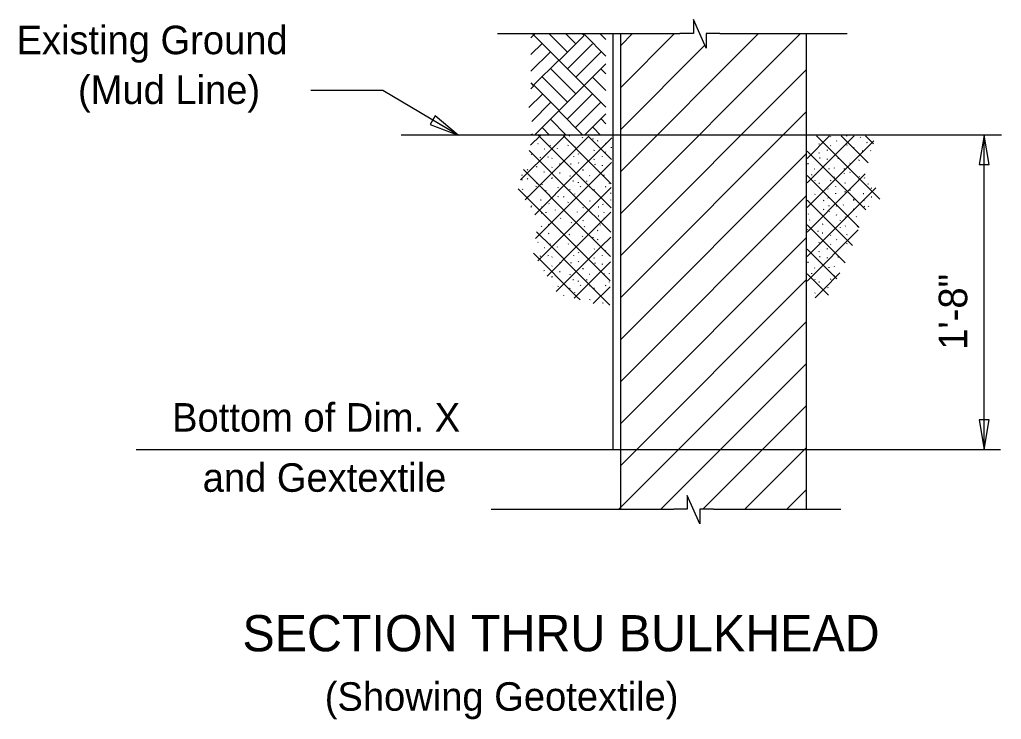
# Model space of a CAD drawing. Extents: x 0.4 to 30.4, y 0.1 to 19.4.
# Drawn here: x 9.23 to 14.44, y 10.56 to 14.27 of the extents above; entities that cross this region are included whole.
import ezdxf

# ---------------------------------------------------------------- set-up
doc = ezdxf.new("R2010")
doc.units = 0
for name, color, linetype in [('Dimension', 7, 'Continuous'), ('Miscellaneous', 7, 'Continuous'), ('Rebar', 7, 'Continuous'), ('SheetPileConc', 7, 'Continuous'), ('TextStructures', 7, 'Continuous')]:
    doc.layers.add(name, color=color, linetype=linetype)

msp = doc.modelspace()

# ---------------------------------------------------------------- linework, layer by layer
at = {"layer": 'Dimension'}
for p, q in [((11.7699, 14.197), (12.738, 14.197)), ((12.9487, 14.197), (13.6252, 14.197)), ((14.3518, 11.9905), (14.3518, 13.6572)), ((9.8519, 11.9905), (14.439, 11.9905)), ((11.737, 11.6738), (12.7051, 11.6738)), ((12.9158, 11.6738), (13.5923, 11.6738))]:
    msp.add_line(p, q, dxfattribs=at)
for points in [[(12.9487, 14.197), (12.8768, 14.197), (12.8768, 14.1188), (12.8099, 14.27), (12.8099, 14.197), (12.738, 14.197)], [(11.5605, 13.6572), (11.1618, 13.8946), (10.7797, 13.8946)], [(12.9158, 11.6738), (12.8439, 11.6738), (12.8439, 11.5957), (12.777, 11.7469), (12.777, 11.6738), (12.7051, 11.6738)]]:
    msp.add_lwpolyline(points, dxfattribs=at)
for points in [[(11.5605, 13.6572), (11.4399, 13.7599), (11.4128, 13.7144)], [(14.3517, 13.6572), (14.3253, 13.501), (14.3782, 13.501)], [(14.3517, 11.9906), (14.3782, 12.1468), (14.3253, 12.1468)]]:
    msp.add_lwpolyline(points, close=True, dxfattribs=at)
at = {"layer": 'Miscellaneous'}
for p, q in [((11.9706, 14.197), (11.9466, 14.1729)), ((12.0946, 14.0559), (11.9534, 14.197)), ((12.042, 14.197), (12.1388, 14.1002)), ((12.23, 14.1858), (12.0974, 14.0531)), ((12.1302, 14.197), (12.1829, 14.1443)), ((12.2188, 14.197), (12.2272, 14.1886)), ((12.2357, 14.197), (12.23, 14.1913)), ((12.3449, 14.0764), (12.2328, 14.1886)), ((12.3449, 14.1647), (12.3126, 14.197)), ((12.4236, 13.2427), (13.378, 14.197)), ((12.4236, 13.9109), (12.7097, 14.197)), ((12.4236, 13.4654), (13.1552, 14.197)), ((12.4236, 14.1336), (12.487, 14.197)), ((12.0062, 14.1443), (11.9466, 14.0847)), ((12.2743, 14.1415), (12.1416, 14.0088)), ((12.4236, 13.6881), (12.8699, 14.1345)), ((12.0503, 14.1002), (11.9466, 13.9964)), ((12.3184, 14.0974), (12.1857, 13.9647)), ((12.0946, 14.0559), (11.9624, 13.9238)), ((12.3449, 13.8056), (12.0974, 14.0531)), ((12.3449, 14.0362), (12.0975, 13.7887)), ((12.1416, 13.8329), (12.0093, 13.9651)), ((12.1859, 13.8772), (12.0536, 14.0094)), ((12.2739, 13.9651), (12.3449, 13.8941)), ((12.318, 14.0093), (12.3449, 13.9824)), ((12.4236, 13.0199), (13.408, 14.0043)), ((11.9466, 13.9341), (11.9597, 13.921)), ((11.9624, 13.9182), (11.9466, 13.9023)), ((12.0975, 13.7887), (11.9652, 13.921)), ((12.0067, 13.8739), (11.9361, 13.8033)), ((12.2737, 13.8768), (12.1416, 13.7446)), ((12.0509, 13.8298), (11.9512, 13.7301)), ((12.3178, 13.8326), (12.1857, 13.7005)), ((12.0947, 13.7859), (11.9661, 13.6572)), ((12.0947, 13.7859), (12.2234, 13.6572)), ((12.3449, 13.771), (12.2311, 13.6572)), ((12.4236, 12.7972), (13.408, 13.7816)), ((12.0504, 13.7417), (12.1348, 13.6572)), ((12.3449, 13.7182), (12.3212, 13.7419)), ((14.4433, 13.6572), (11.2587, 13.6572)), ((11.9455, 13.6035), (11.9975, 13.6555)), ((11.958, 13.6572), (11.9512, 13.6641)), ((12.0578, 13.5856), (11.9878, 13.6556)), ((12.0063, 13.6976), (12.0466, 13.6572)), ((12.0578, 13.5856), (12.1264, 13.6541)), ((12.1878, 13.5858), (12.1194, 13.6542)), ((12.1523, 13.6532), (12.1486, 13.6525)), ((12.1881, 13.5856), (12.2553, 13.6528)), ((12.2215, 13.6441), (12.2223, 13.6472)), ((12.3183, 13.5856), (12.251, 13.6529)), ((12.3172, 13.6572), (12.2769, 13.6976)), ((13.4129, 13.5345), (13.5321, 13.6537)), ((13.4129, 13.4043), (13.6623, 13.6537)), ((13.7576, 13.3588), (13.4626, 13.6537)), ((13.538, 13.6483), (13.5372, 13.6498)), ((13.7367, 13.5099), (13.5928, 13.6537)), ((13.6237, 13.6521), (13.624, 13.6537)), ((13.7578, 13.6189), (13.723, 13.6537)), ((11.9851, 13.6111), (11.9836, 13.6118)), ((12.0513, 13.6028), (12.0506, 13.6043)), ((12.1455, 13.6023), (12.1463, 13.6053)), ((12.1817, 13.5945), (12.1824, 13.5976)), ((12.2772, 13.6359), (12.2779, 13.6389)), ((12.3027, 13.6269), (12.2982, 13.6261)), ((12.3183, 13.5856), (12.3761, 13.6434)), ((12.3441, 13.614), (12.3434, 13.6155)), ((13.4763, 13.61), (13.4778, 13.613)), ((13.4974, 13.3585), (13.7578, 13.619)), ((13.538, 13.601), (13.5372, 13.6025)), ((13.5688, 13.6251), (13.5695, 13.6281)), ((13.6237, 13.6048), (13.6245, 13.6085)), ((13.6959, 13.6454), (13.6944, 13.6461)), ((13.7305, 13.6182), (13.7275, 13.6168)), ((13.7578, 13.6189), (13.7669, 13.628)), ((13.7646, 13.6122), (13.7578, 13.619)), ((13.7621, 13.6371), (13.7613, 13.6386)), ((11.8926, 13.4203), (12.0578, 13.5856)), ((11.9169, 13.3143), (12.1881, 13.5856)), ((12.1881, 13.3251), (11.9375, 13.5757)), ((11.9506, 13.5554), (11.9513, 13.5584)), ((12.0197, 13.584), (12.0167, 13.5825)), ((12.1881, 13.4554), (12.0578, 13.5856)), ((12.0881, 13.5862), (12.0888, 13.5892)), ((12.1749, 13.5419), (12.1757, 13.5449)), ((12.3735, 13.4001), (12.1881, 13.5856)), ((12.1881, 13.4554), (12.3183, 13.5856)), ((12.2005, 13.557), (12.2012, 13.5599)), ((12.2824, 13.5757), (12.2839, 13.5788)), ((12.3749, 13.5289), (12.3183, 13.5856)), ((12.3268, 13.5419), (12.3268, 13.5449)), ((12.3441, 13.5667), (12.3434, 13.5682)), ((12.3749, 13.5908), (12.3756, 13.5936)), ((12.4236, 12.5745), (13.408, 13.5588)), ((13.6276, 13.3585), (13.4129, 13.5732)), ((13.4763, 13.5626), (13.4778, 13.5656)), ((13.5207, 13.5762), (13.5207, 13.5792)), ((13.6613, 13.5897), (13.6621, 13.5927)), ((13.7087, 13.5724), (13.705, 13.5717)), ((13.7508, 13.5739), (13.7493, 13.5762)), ((11.9769, 13.49), (11.9784, 13.493)), ((11.9784, 13.4885), (11.9791, 13.4915)), ((11.9979, 13.5381), (11.9942, 13.5374)), ((12.04, 13.5396), (12.0385, 13.5419)), ((12.0588, 13.5329), (12.0603, 13.5359)), ((12.1022, 13.5036), (12.0984, 13.5028)), ((12.1614, 13.5036), (12.1576, 13.5028)), ((12.1881, 13.3251), (12.3747, 13.5118)), ((12.2005, 13.5088), (12.2012, 13.5118)), ((12.2824, 13.5284), (12.2839, 13.5314)), ((12.2877, 13.5013), (12.2847, 13.5006)), ((12.3268, 13.4945), (12.3268, 13.4975)), ((13.4199, 13.5055), (13.4154, 13.5055)), ((13.4816, 13.5356), (13.4786, 13.5348)), ((13.5207, 13.5288), (13.5207, 13.5318)), ((13.5793, 13.5341), (13.5756, 13.5333)), ((13.6387, 13.5063), (13.641, 13.5092)), ((13.6876, 13.5243), (13.6891, 13.5273)), ((13.6891, 13.5228), (13.6899, 13.5258)), ((11.9002, 13.4434), (11.9009, 13.4464)), ((12.1881, 13.1949), (11.9083, 13.4746)), ((11.928, 13.472), (11.9302, 13.4749)), ((11.9678, 13.235), (12.1881, 13.4554)), ((12.0197, 13.4599), (12.0182, 13.4622)), ((12.0588, 13.4855), (12.0603, 13.4885)), ((12.1022, 13.4562), (12.0984, 13.4554)), ((12.1557, 13.4404), (12.1565, 13.4434)), ((12.3721, 13.2713), (12.1881, 13.4554)), ((12.226, 13.4712), (12.2215, 13.4712)), ((12.2599, 13.4419), (12.2584, 13.4426)), ((12.335, 13.4434), (12.3358, 13.4464)), ((12.3644, 13.4479), (12.3637, 13.4494)), ((13.4974, 13.3585), (13.4129, 13.443)), ((13.4372, 13.4461), (13.438, 13.449)), ((13.4538, 13.4762), (13.4523, 13.4769)), ((13.5289, 13.4777), (13.5297, 13.4807)), ((13.5583, 13.4822), (13.5576, 13.4837)), ((13.6109, 13.4777), (13.6117, 13.4807)), ((13.6109, 13.4536), (13.6117, 13.4566)), ((13.6276, 13.3585), (13.7209, 13.4518)), ((13.6387, 13.4589), (13.641, 13.4619)), ((11.9002, 13.4193), (11.9009, 13.4223)), ((11.928, 13.4246), (11.9302, 13.4276)), ((11.9746, 13.3855), (11.9761, 13.3886)), ((11.9784, 13.4013), (11.9791, 13.4043)), ((12.0069, 13.3952), (12.0084, 13.399)), ((12.058, 13.4276), (12.0573, 13.4291)), ((12.0611, 13.4299), (12.058, 13.4299)), ((12.1734, 13.414), (12.1697, 13.4133)), ((12.1802, 13.3915), (12.1798, 13.3923)), ((12.199, 13.405), (12.1997, 13.4081)), ((12.2103, 13.3832), (12.2118, 13.387)), ((12.2434, 13.4118), (12.2441, 13.4148)), ((12.3644, 13.4006), (12.3637, 13.4021)), ((13.4546, 13.4145), (13.4561, 13.4175)), ((13.4786, 13.4017), (13.4749, 13.4009)), ((13.538, 13.4175), (13.5343, 13.416)), ((13.5583, 13.4348), (13.5576, 13.4363)), ((13.6139, 13.4032), (13.6155, 13.4069)), ((13.6854, 13.4198), (13.6869, 13.4228)), ((13.6891, 13.4356), (13.6899, 13.4386)), ((13.7177, 13.4295), (13.7192, 13.4333)), ((13.7372, 13.3972), (13.738, 13.4002)), ((12.1878, 13.0649), (11.8791, 13.3736)), ((11.9032, 13.369), (11.9047, 13.3727)), ((12.0265, 13.3629), (12.0272, 13.366)), ((12.0446, 13.3412), (12.0423, 13.3419)), ((12.0919, 13.378), (12.0934, 13.381)), ((12.1542, 13.3675), (12.1549, 13.3705)), ((12.1802, 13.3442), (12.1794, 13.3456)), ((12.1881, 13.1949), (12.3733, 13.3801)), ((12.2607, 13.3802), (12.2622, 13.3832)), ((12.2847, 13.3675), (12.281, 13.3667)), ((12.3306, 13.3359), (12.3283, 13.3382)), ((12.3441, 13.3832), (12.3404, 13.3817)), ((12.3704, 13.3487), (12.3712, 13.3516)), ((12.4236, 12.3517), (13.408, 13.3361)), ((13.4129, 13.0136), (13.7578, 13.3585)), ((13.4129, 13.274), (13.4974, 13.3585)), ((13.4129, 13.1438), (13.6276, 13.3585)), ((13.4541, 13.3419), (13.4549, 13.3448)), ((13.6887, 13.1672), (13.4974, 13.3585)), ((13.5245, 13.3702), (13.5222, 13.3724)), ((13.5643, 13.383), (13.5651, 13.3859)), ((13.5651, 13.3461), (13.5658, 13.3491)), ((13.6139, 13.3558), (13.6155, 13.3596)), ((13.724, 13.2621), (13.6276, 13.3585)), ((13.641, 13.3642), (13.6417, 13.3671)), ((13.7132, 13.3468), (13.7094, 13.3461)), ((13.7553, 13.3754), (13.7531, 13.3761)), ((13.7578, 13.3585), (13.7772, 13.3779)), ((13.7979, 13.3184), (13.7578, 13.3585)), ((11.9302, 13.3299), (11.931, 13.3328)), ((11.9506, 13.2817), (11.9513, 13.2848)), ((11.9722, 13.1093), (12.1881, 13.3251)), ((12.0024, 13.3125), (11.9986, 13.3118)), ((12.0446, 13.2938), (12.0423, 13.2945)), ((12.0919, 13.3306), (12.0934, 13.3336)), ((12.1214, 13.3289), (12.1221, 13.332)), ((12.1452, 13.3007), (12.1459, 13.3037)), ((12.3707, 13.1425), (12.1881, 13.3251)), ((12.2602, 13.3076), (12.261, 13.3106)), ((12.3306, 13.2886), (12.3283, 13.2908)), ((12.3712, 13.3118), (12.3719, 13.3149)), ((13.6536, 13.072), (13.4129, 13.3127)), ((13.4184, 13.3069), (13.4191, 13.31)), ((13.5019, 13.31), (13.4981, 13.3092)), ((13.5245, 13.3228), (13.5222, 13.325)), ((13.5289, 13.2806), (13.5297, 13.2837)), ((13.5688, 13.2806), (13.5695, 13.2837)), ((13.6041, 13.2856), (13.6049, 13.2885)), ((13.6598, 13.3107), (13.6613, 13.3138)), ((13.6613, 13.316), (13.6621, 13.319)), ((13.7143, 13.309), (13.715, 13.312)), ((13.7387, 13.2799), (13.7395, 13.2829)), ((13.7553, 13.328), (13.7531, 13.3288)), ((11.949, 13.2764), (11.9506, 13.2795)), ((12.0054, 13.2442), (12.0024, 13.2434)), ((12.0035, 13.2748), (12.0043, 13.2777)), ((12.028, 13.2456), (12.0287, 13.2486)), ((12.0769, 13.2592), (12.0776, 13.2622)), ((12.123, 13.257), (12.1245, 13.26)), ((12.1881, 13.0647), (12.3718, 13.2485)), ((12.1945, 13.2486), (12.1952, 13.2516)), ((12.2245, 13.2727), (12.2253, 13.2757)), ((12.308, 13.2757), (12.3042, 13.2749)), ((12.335, 13.2464), (12.3358, 13.2494)), ((13.4184, 13.2378), (13.4191, 13.2408)), ((13.5019, 13.2627), (13.4981, 13.2619)), ((13.5315, 13.2504), (13.5322, 13.2534)), ((13.5688, 13.2333), (13.5695, 13.2363)), ((13.6598, 13.2634), (13.6613, 13.2664)), ((13.7162, 13.2784), (13.7132, 13.2776)), ((12.0415, 13.1832), (12.0385, 13.1817)), ((12.0578, 13.0647), (12.1881, 13.1949)), ((12.1036, 13.2149), (12.1051, 13.2178)), ((12.1644, 13.1915), (12.1629, 13.1938)), ((12.3183, 13.0647), (12.1881, 13.1949)), ((12.2245, 13.2035), (12.2253, 13.2065)), ((12.308, 13.2284), (12.3042, 13.2276)), ((12.3163, 13.1795), (12.3171, 13.1824)), ((12.3376, 13.2162), (12.3383, 13.2191)), ((13.6145, 12.9809), (13.4129, 13.1825)), ((13.426, 13.2058), (13.4268, 13.2088)), ((13.4966, 13.1851), (13.4921, 13.1844)), ((13.5102, 13.2138), (13.5109, 13.2167)), ((13.5891, 13.2025), (13.5899, 13.2054)), ((13.6169, 13.2235), (13.6139, 13.2228)), ((13.6749, 13.2235), (13.6726, 13.2258)), ((12.0578, 13.0647), (11.9775, 13.1451)), ((12.0032, 13.1734), (12.0047, 13.1764)), ((12.0415, 13.1358), (12.0385, 13.1344)), ((12.1052, 13.1442), (12.1037, 13.1464)), ((12.1523, 13.1299), (12.1486, 13.1291)), ((12.2321, 13.1716), (12.2329, 13.1745)), ((12.3027, 13.1509), (12.2982, 13.1501)), ((13.4129, 12.8834), (13.684, 13.1545)), ((13.4154, 13.1551), (13.4162, 13.1581)), ((13.4711, 13.1468), (13.4718, 13.1498)), ((13.4966, 13.1378), (13.4921, 13.137)), ((13.538, 13.125), (13.5372, 13.1265)), ((13.5891, 13.1671), (13.5899, 13.1701)), ((13.6169, 13.1761), (13.6139, 13.1754)), ((13.6237, 13.1287), (13.6245, 13.1325)), ((13.6801, 13.1717), (13.6809, 13.1746)), ((11.9851, 13.0878), (11.9836, 13.0885)), ((12.0513, 13.0794), (12.0506, 13.0809)), ((12.1455, 13.0789), (12.1463, 13.0819)), ((12.1817, 13.0712), (12.1824, 13.0742)), ((12.2215, 13.1208), (12.2223, 13.1238)), ((12.2772, 13.1125), (12.2779, 13.1156)), ((12.3027, 13.1035), (12.2982, 13.1027)), ((12.3183, 13.0647), (12.3704, 13.1168)), ((12.3441, 13.0907), (12.3434, 13.0922)), ((12.4236, 12.129), (13.408, 13.1133)), ((13.4763, 13.0866), (13.4778, 13.0897)), ((13.538, 13.0776), (13.5372, 13.0791)), ((13.5688, 13.1017), (13.5695, 13.1047)), ((13.6237, 13.0814), (13.6245, 13.0851)), ((12.1881, 12.8042), (11.9608, 13.0315)), ((11.9843, 12.9911), (12.0578, 13.0647)), ((12.0197, 13.0606), (12.0167, 13.0592)), ((12.0331, 12.9097), (12.1881, 13.0647)), ((12.1881, 12.9345), (12.0578, 13.0647)), ((12.0881, 13.0629), (12.0888, 13.0659)), ((12.3679, 12.8848), (12.1881, 13.0647)), ((12.1881, 12.9345), (12.3183, 13.0647)), ((12.2005, 13.0336), (12.2012, 13.0366)), ((12.2824, 13.0524), (12.2839, 13.0554)), ((12.3693, 13.0136), (12.3183, 13.0647)), ((12.3441, 13.0434), (12.3434, 13.0449)), ((13.57, 12.8952), (13.4129, 13.0523)), ((13.4763, 13.0393), (13.4778, 13.0423)), ((13.5207, 13.0528), (13.5207, 13.0558)), ((11.9979, 13.0148), (11.9942, 13.0141)), ((12.04, 13.0163), (12.0385, 13.0186)), ((12.0588, 13.0095), (12.0603, 13.0125)), ((12.1022, 12.9802), (12.0984, 12.9794)), ((12.1614, 12.9802), (12.1576, 12.9794)), ((12.1749, 13.0186), (12.1757, 13.0216)), ((12.1881, 12.8042), (12.369, 12.9851)), ((12.2005, 12.9854), (12.2012, 12.9885)), ((12.2824, 13.005), (12.2839, 13.008)), ((12.2877, 12.9779), (12.2847, 12.9772)), ((12.3268, 13.0186), (12.3268, 13.0216)), ((12.3268, 12.9712), (12.3268, 12.9742)), ((13.4199, 12.9821), (13.4154, 12.9821)), ((13.4816, 13.0122), (13.4786, 13.0115)), ((13.5207, 13.0054), (13.5207, 13.0084)), ((13.5793, 13.0107), (13.5756, 13.0099)), ((12.0197, 12.9366), (12.0182, 12.9389)), ((12.0588, 12.9621), (12.0603, 12.9652)), ((12.0819, 12.8283), (12.1881, 12.9345)), ((12.1022, 12.9328), (12.0984, 12.932)), ((12.1557, 12.9171), (12.1565, 12.9201)), ((12.3665, 12.756), (12.1881, 12.9345)), ((12.226, 12.9479), (12.2215, 12.9479)), ((12.2599, 12.9186), (12.2584, 12.9193)), ((12.335, 12.9201), (12.3358, 12.9231)), ((12.3644, 12.9246), (12.3637, 12.9261)), ((13.4974, 12.8376), (13.4129, 12.9221)), ((13.4372, 12.9228), (13.438, 12.9257)), ((13.4538, 12.9528), (13.4523, 12.9536)), ((13.4974, 12.8376), (13.5864, 12.9266)), ((13.5289, 12.9543), (13.5297, 12.9573)), ((13.5583, 12.9588), (13.5576, 12.9603)), ((12.058, 12.9042), (12.0573, 12.9057)), ((12.0611, 12.9065), (12.058, 12.9065)), ((12.1734, 12.8907), (12.1697, 12.89)), ((12.1802, 12.8681), (12.1798, 12.869)), ((12.199, 12.8817), (12.1997, 12.8847)), ((12.2434, 12.8885), (12.2441, 12.8914)), ((12.3644, 12.8772), (12.3637, 12.8787)), ((12.4236, 11.9062), (13.408, 12.8906)), ((13.4546, 12.8911), (13.4561, 12.8941)), ((13.4786, 12.8784), (13.4749, 12.8776)), ((13.538, 12.8941), (13.5343, 12.8926)), ((13.5583, 12.9115), (13.5576, 12.913)), ((12.0919, 12.8547), (12.0934, 12.8577)), ((12.1542, 12.8441), (12.1549, 12.8472)), ((12.1802, 12.8208), (12.1794, 12.8223)), ((12.2103, 12.8599), (12.2118, 12.8636)), ((12.2607, 12.8569), (12.2622, 12.8599)), ((12.2783, 12.7642), (12.3675, 12.8535)), ((12.2847, 12.8441), (12.281, 12.8433)), ((12.3306, 12.8125), (12.3283, 12.8148)), ((12.3441, 12.8599), (12.3404, 12.8584)), ((13.4541, 12.8186), (13.4549, 12.8215)), ((13.4546, 12.7948), (13.4974, 12.8376)), ((13.5255, 12.8095), (13.4974, 12.8376)), ((13.5245, 12.8468), (13.5222, 12.8491)), ((12.1218, 12.8072), (12.1221, 12.8086)), ((12.1761, 12.7923), (12.1881, 12.8042)), ((12.2091, 12.7832), (12.1881, 12.8042)), ((12.2602, 12.7843), (12.261, 12.7872)), ((12.3306, 12.7652), (12.3283, 12.7674)), ((12.4139, 11.6738), (13.408, 12.6679)), ((12.6367, 11.6738), (13.408, 12.4451)), ((12.8594, 11.6738), (13.408, 12.2224)), ((13.0822, 11.6738), (13.408, 11.9997)), ((13.3049, 11.6738), (13.408, 11.7769))]:
    msp.add_line(p, q, dxfattribs=at)
at = {"layer": 'Rebar'}
msp.add_line((12.3842, 11.9905), (12.3842, 14.197), dxfattribs=at)
at = {"layer": 'SheetPileConc'}
for p, q in [((12.4236, 11.6738), (12.4236, 14.197)), ((13.408, 14.197), (13.408, 11.6738))]:
    msp.add_line(p, q, dxfattribs=at)

# ---------------------------------------------------------------- texts
at = {"layer": 'Dimension'}
for s, p in [('Existing Ground', (9.2178, 14.0867)), ('(Mud Line)', (9.5441, 13.8227)), ('Bottom of Dim. X', (10.0435, 12.0852)), ('and Gextextile', (10.2057, 11.766))]:
    msp.add_text(s, height=0.1512, dxfattribs=at).set_placement(p)
at = {"layer": 'TextStructures'}
msp.add_text('1\'-8"', height=0.1512, rotation=90, dxfattribs=at).set_placement((14.2621, 12.5191))
for s, height, p in [('SECTION THRU BULKHEAD', 0.192, (10.4165, 10.92)), ('(Showing Geotextile)', 0.1512, (10.8533, 10.6048))]:
    msp.add_text(s, height=height, dxfattribs=at).set_placement(p)

doc.saveas('drawing.dxf')
